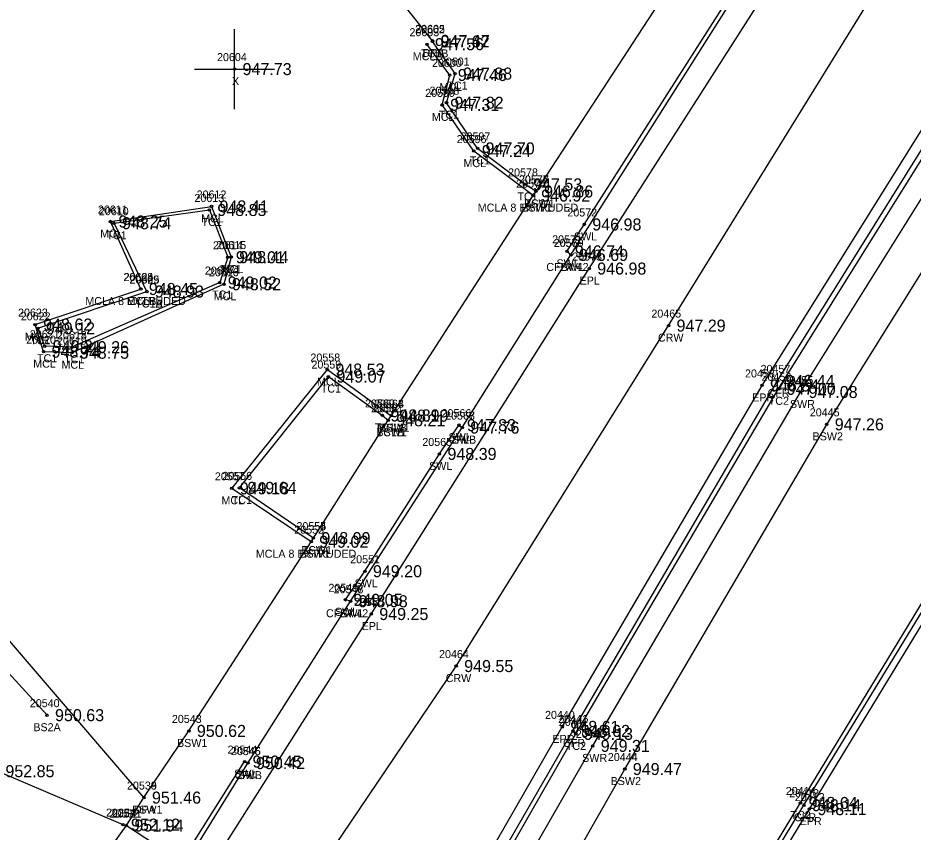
# Model space of a CAD drawing. Extents: x 1576181 to 1577685, y 1099396 to 1101490.
# Drawn here: x 1576415.2 to 1576527.1, y 1099665.2 to 1099766.9 of the extents above; entities that cross this region are included whole.
import ezdxf

# ---------------------------------------------------------------- set-up
doc = ezdxf.new("R2010")
doc.units = 0
for name, color, linetype in [('RD_DTM_BkLn1', 7, 'Continuous'), ('RD_DTM_BkLn2', 7, 'Continuous'), ('RD_DTM_BkLn_txCode', 7, 'Continuous'), ('RD_EX_Conc', 7, 'Continuous'), ('RD_EX_Conc_txCode', 7, 'Continuous'), ('RD_EX_Driveway', 7, 'Continuous'), ('RD_EX_Driveway_txCode', 7, 'Continuous'), ('RD_EX_Misc', 7, 'Continuous'), ('RD_EX_Misc_txCode', 7, 'Continuous'), ('RD_EX_Road', 7, 'Continuous'), ('RD_EX_Road_txCode', 7, 'Continuous'), ('RD_EX_TX_Conc_ELEV', 7, 'Continuous'), ('RD_EX_TX_Driveway_ELEV', 7, 'Continuous'), ('RD_EX_TX_Misc_ELEV', 7, 'Continuous'), ('RD_EX_TX_Road_ELEV', 7, 'Continuous'), ('RD_HC_Survey_ELEV', 7, 'Continuous'), ('RD_HC_Survey_txCode', 7, 'Continuous'), ('RD_SMD_Locator', 7, 'Continuous')]:
    doc.layers.add(name, color=color, linetype=linetype)

msp = doc.modelspace()

# ---------------------------------------------------------------- linework, layer by layer
at = {"layer": 'RD_DTM_BkLn1'}
msp.add_lwpolyline([(1576435.96, 1099635.47), (1576469.98, 1099685.91), (1576496.51, 1099728.46), (1576522.67, 1099770.85), (1576549.06, 1099813.4), (1576563.36, 1099837.2), (1576575.09, 1099855.95), (1576600.75, 1099898.96), (1576625.57, 1099942.14), (1576652.37, 1099988.91), (1576675.03, 1100029.12), (1576699.51, 1100072.44), (1576723.52, 1100115.7), (1576748.08, 1100158.53), (1576774.13, 1100203.85), (1576797.97, 1100246.52), (1576822.46, 1100289.82), (1576846.93, 1100333.35), (1576871.37, 1100376.46), (1576888.27, 1100406.22)], dxfattribs=at)
at = {"layer": 'RD_DTM_BkLn2'}
msp.add_line((1576418.86, 1099679.77), (1576392.78, 1099708.39), dxfattribs=at)
for points in [[(1576271.23, 1099836.06), (1576304.3, 1099797.36), (1576339.24, 1099758.21), (1576368.71, 1099722.87), (1576388.13, 1099699.72), (1576412.66, 1099672.77), (1576428.35, 1099666.09)], [(1576453.65, 1099622.74), (1576484.93, 1099677.43), (1576510.27, 1099720.56), (1576537.09, 1099763.56), (1576564.3, 1099806.82), (1576572.37, 1099816.55), (1576577.32, 1099819.84)], [(1576479.96, 1099745.23), (1576478.59, 1099746.11), (1576472.65, 1099750.61), (1576468.77, 1099756.32), (1576469.84, 1099759.96), (1576467.02, 1099763.98)], [(1576431.33, 1099732.72), (1576427.24, 1099741.26), (1576439.14, 1099742.91), (1576441.45, 1099737), (1576440.44, 1099733.84), (1576421.97, 1099725.76), (1576418.57, 1099725.88), (1576417.72, 1099728.12), (1576431.33, 1099732.72)], [(1576511.92, 1099607.05), (1576510.37, 1099614.53), (1576509.23, 1099617.04), (1576507.41, 1099618.75), (1576489.23, 1099629.49), (1576513, 1099668.8), (1576536.11, 1099706.87), (1576550.83, 1099731.33)], [(1576452.14, 1099701.9), (1576442.9, 1099708.18), (1576454.02, 1099722.09), (1576460.77, 1099717.23), (1576461.49, 1099716.63)]]:
    msp.add_lwpolyline(points, dxfattribs=at)
at = {"layer": 'RD_EX_Conc'}
for p, q in [((1576456.79, 1099694.01), (1576470.74, 1099715.71)), ((1576436.12, 1099661.14), (1576443.97, 1099673.78))]:
    msp.add_line(p, q, dxfattribs=at)
for points in [[(1576435.66, 1099661.47), (1576443.54, 1099673.97), (1576443.97, 1099673.78), (1576456.79, 1099694.01), (1576456.14, 1099694.19), (1576458.58, 1099697.76), (1576467.89, 1099712.42), (1576470.32, 1099716.02), (1576470.74, 1099715.71), (1576484.32, 1099737.29), (1576483.81, 1099737.74), (1576485.99, 1099741.1), (1576511.43, 1099781.01), (1576536.53, 1099821.05), (1576540.61, 1099827.59), (1576541.13, 1099827.37), (1576542.92, 1099831.85), (1576542.87, 1099835.12), (1576541.33, 1099839.59)], [(1576484.32, 1099737.29), (1576511.76, 1099780.7), (1576536.95, 1099820.66), (1576541.42, 1099827.15)], [(1576450.24, 1099618.33), (1576484.56, 1099677.8), (1576510.13, 1099721.55), (1576536.54, 1099763.94), (1576563.69, 1099807.11), (1576571.96, 1099817.02), (1576576.78, 1099820.05)], [(1576453.65, 1099622.74), (1576455.84, 1099621.56), (1576487.04, 1099675.93), (1576513, 1099720.16), (1576539.03, 1099761.82), (1576566.5, 1099805.38), (1576570.9, 1099812.6)], [(1576460.33, 1099619.05), (1576491.05, 1099673.04), (1576516.28, 1099716.12), (1576543.31, 1099759.42), (1576570.5, 1099802.59), (1576575.6, 1099809.12)], [(1576428.78, 1099665.98), (1576430.97, 1099669.47), (1576436.58, 1099677.8), (1576451.87, 1099701.45), (1576452.14, 1099701.9), (1576461.49, 1099716.63), (1576461.87, 1099717.2), (1576479.6, 1099744.71), (1576479.96, 1099745.23), (1576504.22, 1099782.43), (1576509.78, 1099791.57)], [(1576479.6, 1099744.71), (1576472.18, 1099750.27), (1576468.23, 1099756.05), (1576469.18, 1099759.78), (1576466.32, 1099763.63)], [(1576430.58, 1099733.03), (1576426.79, 1099741.47), (1576439.41, 1099743.35), (1576441.88, 1099737.02), (1576440.97, 1099733.63), (1576421.97, 1099725.07), (1576418.43, 1099725.2), (1576417.38, 1099728.59), (1576430.58, 1099733.03)], [(1576512.55, 1099607.18), (1576510.94, 1099614.7), (1576509.78, 1099617.42), (1576507.67, 1099619.31), (1576489.95, 1099629.7), (1576513.43, 1099668.52), (1576536.7, 1099706.66), (1576550.99, 1099730.5)], [(1576451.87, 1099701.45), (1576441.95, 1099708.12), (1576453.89, 1099722.97), (1576461.87, 1099717.2)]]:
    msp.add_lwpolyline(points, dxfattribs=at)
at = {"layer": 'RD_EX_Driveway'}
for p, q in [((1576467.04, 1099764.05), (1576453.88, 1099780.69)), ((1576430.97, 1099669.47), (1576396.23, 1099709.97))]:
    msp.add_line(p, q, dxfattribs=at)
at = {"layer": 'RD_EX_Misc'}
for p, q in [((1576442.29, 1099755.52), (1576442.29, 1099765.52)), ((1576437.29, 1099760.52), (1576447.29, 1099760.52))]:
    msp.add_line(p, q, dxfattribs=at)
at = {"layer": 'RD_EX_Road'}
for points in [[(1576217.78, 1099763.81), (1576263.48, 1099736.46), (1576283.45, 1099724.57), (1576282.38, 1099722.88), (1576302.5, 1099710.8), (1576345.46, 1099684.21), (1576368.62, 1099668.36), (1576383.76, 1099654.94), (1576386.09, 1099656.79), (1576408.06, 1099639.92), (1576408.06, 1099639.92), (1576411.91, 1099642.96), (1576420.57, 1099654.58), (1576428.78, 1099665.98), (1576435.66, 1099661.47), (1576436.12, 1099661.14), (1576438.46, 1099659.42), (1576459.37, 1099692.41), (1576486.6, 1099735.59), (1576512.85, 1099776.73), (1576539.46, 1099818.98), (1576543.78, 1099825.47), (1576541.42, 1099827.15), (1576542.92, 1099831.85)], [(1576450.24, 1099618.33), (1576449.12, 1099618.92), (1576483.24, 1099678.31), (1576508.19, 1099720.98), (1576535.39, 1099764.56), (1576562.56, 1099807.86), (1576568.65, 1099815.29), (1576571.43, 1099817.5), (1576576.56, 1099821.02), (1576582.03, 1099822.66), (1576588.16, 1099823.79), (1576596.81, 1099822.84), (1576604.56, 1099819.9), (1576624.36, 1099808.15), (1576638.14, 1099802.71)], [(1576513.37, 1099607.48), (1576511.79, 1099614.93), (1576510.39, 1099617.93), (1576508.02, 1099620.01), (1576491.05, 1099629.97), (1576514.12, 1099668.03), (1576537.42, 1099706.25), (1576551.23, 1099729.3)]]:
    msp.add_lwpolyline(points, dxfattribs=at)
at = {"layer": 'RD_SMD_Locator'}
for centre in [(1576467.02, 1099763.98), (1576467.04, 1099764.05), (1576466.32, 1099763.63), (1576442.29, 1099760.52), (1576469.18, 1099759.78), (1576469.84, 1099759.96), (1576468.23, 1099756.05), (1576468.77, 1099756.32), (1576472.65, 1099750.61), (1576472.18, 1099750.27), (1576478.59, 1099746.11), (1576479.96, 1099745.23), (1576479.96, 1099745.23), (1576479.6, 1099744.71), (1576479.6, 1099744.71), (1576439.14, 1099742.91), (1576439.41, 1099743.35), (1576426.79, 1099741.47), (1576427.24, 1099741.26), (1576485.99, 1099741.1), (1576441.45, 1099737), (1576441.88, 1099737.02), (1576483.81, 1099737.74), (1576484.32, 1099737.29), (1576484.32, 1099737.29), (1576486.6, 1099735.59), (1576440.44, 1099733.84), (1576440.97, 1099733.63), (1576430.58, 1099733.03), (1576430.58, 1099733.03), (1576431.33, 1099732.72), (1576431.33, 1099732.72), (1576417.38, 1099728.59), (1576417.72, 1099728.12), (1576496.51, 1099728.46), (1576418.57, 1099725.88), (1576418.43, 1099725.2), (1576421.97, 1099725.76), (1576421.97, 1099725.07), (1576453.89, 1099722.97), (1576454.02, 1099722.09), (1576510.13, 1099721.55), (1576508.19, 1099720.98), (1576510.27, 1099720.56), (1576513, 1099720.16), (1576460.77, 1099717.23), (1576461.87, 1099717.2), (1576461.87, 1099717.2), (1576461.49, 1099716.63), (1576461.49, 1099716.63), (1576470.32, 1099716.02), (1576516.28, 1099716.12), (1576470.74, 1099715.71), (1576470.74, 1099715.71), (1576467.89, 1099712.42), (1576441.95, 1099708.12), (1576442.9, 1099708.18), (1576451.87, 1099701.45), (1576451.87, 1099701.45), (1576452.14, 1099701.9), (1576452.14, 1099701.9), (1576458.58, 1099697.76), (1576456.14, 1099694.19), (1576456.79, 1099694.01), (1576456.79, 1099694.01), (1576459.37, 1099692.41), (1576469.98, 1099685.91), (1576418.86, 1099679.77), (1576436.58, 1099677.8), (1576483.24, 1099678.31), (1576484.56, 1099677.8), (1576484.93, 1099677.43), (1576487.04, 1099675.93), (1576443.54, 1099673.97), (1576443.97, 1099673.78), (1576443.97, 1099673.78), (1576491.05, 1099673.04), (1576430.97, 1099669.47), (1576430.97, 1099669.47), (1576513, 1099668.8), (1576513.43, 1099668.52), (1576514.12, 1099668.03), (1576428.35, 1099666.09), (1576428.78, 1099665.98), (1576428.78, 1099665.98)]:
    msp.add_circle(centre, 0.15, dxfattribs=at)

# ---------------------------------------------------------------- texts
at = {"layer": 'RD_DTM_BkLn_txCode'}
for s, p in [('20540', (1576416.71, 1099680.77)), ('BS2A', (1576417.15, 1099677.77)), ('20254', (1576426.23, 1099667.09))]:
    msp.add_text(s, height=1, dxfattribs=at).set_placement(p)
at = {"layer": 'RD_EX_Conc_txCode'}
for s, p in [('20603', (1576464.14, 1099764.63)), ('20602', (1576464.84, 1099764.98)), ('TC1B', (1576465.59, 1099761.98)), ('MCLB', (1576464.55, 1099761.63)), ('20600', (1576466.96, 1099760.78)), ('20601', (1576467.94, 1099760.96)), ('MCL', (1576467.89, 1099757.78)), ('TC1', (1576468.88, 1099757.96)), ('20599', (1576466.11, 1099757.05)), ('20598', (1576466.65, 1099757.32)), ('MCL', (1576466.94, 1099754.05)), ('TC1', (1576467.81, 1099754.32)), ('20596', (1576470.04, 1099751.27)), ('20597', (1576470.53, 1099751.61)), ('TC1', (1576471.69, 1099748.61)), ('MCL', (1576470.89, 1099748.27)), ('20578', (1576476.47, 1099747.11)), ('20576', (1576477.82, 1099746.23)), ('20577', (1576477.84, 1099746.23)), ('20574', (1576477.48, 1099745.71)), ('20575', (1576477.48, 1099745.71)), ('20612', (1576437.55, 1099744.35)), ('TC1', (1576477.63, 1099744.11)), ('20613', (1576437.28, 1099743.91)), ('TC1A', (1576478.51, 1099743.23)), ('BSW1', (1576478.48, 1099743.23)), ('20611', (1576425.22, 1099742.47)), ('20610', (1576425.34, 1099742.26)), ('MCLA 8 EXTRUDED', (1576472.67, 1099742.71)), ('BSW1', (1576478.12, 1099742.71)), ('20572', (1576483.87, 1099742.1)), ('TC1', (1576438.18, 1099740.91)), ('MCL', (1576438.12, 1099741.35)), ('MCL', (1576425.5, 1099739.47)), ('TC1', (1576426.28, 1099739.26)), ('20571', (1576481.97, 1099738.74)), ('SWL', (1576484.7, 1099739.1)), ('20614', (1576439.59, 1099738)), ('20615', (1576440.02, 1099738.02)), ('20570', (1576482.16, 1099738.29)), ('20569', (1576482.18, 1099738.29)), ('TC1', (1576440.49, 1099735)), ('MCL', (1576440.58, 1099735.02)), ('CFLA 42', (1576481.24, 1099735.29)), ('SWL', (1576482.52, 1099735.74)), ('SWL', (1576483.03, 1099735.29)), ('20608', (1576428.4, 1099734.03)), ('20624', (1576428.44, 1099734.03)), ('20617', (1576438.58, 1099734.84)), ('20616', (1576439.09, 1099734.63)), ('20609', (1576429.15, 1099733.72)), ('20625', (1576429.19, 1099733.72)), ('TC1', (1576439.48, 1099731.84)), ('MCL', (1576439.68, 1099731.63)), ('MCLA 8 EXTRUDED', (1576423.65, 1099731.03)), ('MCLB', (1576428.81, 1099731.03)), ('TC1A', (1576429.88, 1099730.72)), ('TC1B', (1576429.9, 1099730.72)), ('20623', (1576415.24, 1099729.59)), ('20622', (1576415.58, 1099729.12)), ('MCL', (1576416.09, 1099726.59)), ('20620', (1576416.25, 1099726.2)), ('20621', (1576416.71, 1099726.88)), ('TC1', (1576416.76, 1099726.12)), ('20619', (1576420.11, 1099726.07)), ('20618', (1576420.11, 1099726.76)), ('TC1', (1576417.61, 1099723.88)), ('20558', (1576451.77, 1099723.97)), ('MCL', (1576417.14, 1099723.2)), ('MCL', (1576420.67, 1099723.07)), ('TC1', (1576421.01, 1099723.76)), ('20559', (1576451.9, 1099723.09)), ('20457', (1576508.01, 1099722.55)), ('MCL', (1576452.59, 1099720.97)), ('20456', (1576508.13, 1099721.56)), ('20455', (1576510.88, 1099721.16)), ('TC1', (1576453.06, 1099720.09)), ('CFR', (1576508.9, 1099719.55)), ('20560', (1576458.59, 1099718.23)), ('TC2', (1576509.03, 1099718.56)), ('20562', (1576459.35, 1099717.63)), ('20561', (1576459.63, 1099717.63)), ('20563', (1576459.72, 1099718.2)), ('20564', (1576459.72, 1099718.2)), ('SWR', (1576511.68, 1099718.16)), ('20445', (1576514.16, 1099717.12)), ('20566', (1576468.15, 1099717.02)), ('20567', (1576468.6, 1099716.71)), ('20568', (1576468.6, 1099716.71)), ('TC1', (1576459.81, 1099715.23)), ('MCLB', (1576460.1, 1099715.2)), ('BSW1', (1576460.38, 1099715.2)), ('TC1B', (1576460.06, 1099714.63)), ('BSW1', (1576460.01, 1099714.63)), ('SWL', (1576469.03, 1099714.02)), ('BSW2', (1576514.51, 1099714.12)), ('20565', (1576465.75, 1099713.42)), ('CFLB', (1576469.06, 1099713.71)), ('SWL', (1576469.45, 1099713.71)), ('SWL', (1576466.6, 1099710.42)), ('20557', (1576439.83, 1099709.12)), ('20556', (1576440.76, 1099709.18)), ('MCL', (1576440.65, 1099706.12)), ('TC1', (1576441.94, 1099706.18)), ('20554', (1576450.02, 1099702.9)), ('20555', (1576450.02, 1099702.9)), ('20552', (1576449.75, 1099702.45)), ('20553', (1576449.75, 1099702.45)), ('MCLA 8 EXTRUDED', (1576444.94, 1099699.45)), ('BSW1', (1576450.39, 1099699.45)), ('TC1A', (1576450.69, 1099699.9)), ('BSW1', (1576450.66, 1099699.9)), ('20551', (1576456.74, 1099698.76)), ('20549', (1576454.02, 1099695.19)), ('20547', (1576454.67, 1099695.01)), ('20548', (1576454.67, 1099695.01)), ('SWL', (1576457.29, 1099695.76)), ('CFLA 42', (1576453.71, 1099692.01)), ('SWL', (1576454.84, 1099692.19)), ('SWL', (1576455.5, 1099692.01)), ('20543', (1576434.46, 1099678.8)), ('20441', (1576482.72, 1099678.8)), ('20442', (1576482.81, 1099678.43)), ('20443', (1576484.92, 1099676.93)), ('BSW1', (1576435.1, 1099675.8)), ('CFR', (1576483.33, 1099675.8)), ('20544', (1576441.42, 1099674.97)), ('20546', (1576441.83, 1099674.78)), ('20545', (1576441.85, 1099674.78)), ('TC2', (1576483.68, 1099675.43)), ('SWR', (1576485.72, 1099673.93)), ('20444', (1576488.93, 1099674.04)), ('SWL', (1576442.25, 1099671.97)), ('CFLB', (1576442.29, 1099671.78)), ('SWL', (1576442.68, 1099671.78)), ('20538', (1576428.85, 1099670.47)), ('BSW2', (1576489.28, 1099671.04)), ('20414', (1576511.16, 1099669.8)), ('20413', (1576511.59, 1099669.52)), ('20532', (1576426.66, 1099666.98)), ('BSW1', (1576429.49, 1099667.47)), ('TC2', (1576511.75, 1099666.8)), ('CFR', (1576512.2, 1099666.52))]:
    msp.add_text(s, height=1, dxfattribs=at).set_placement(p)
at = {"layer": 'RD_EX_Driveway_txCode'}
for s, p in [('20605', (1576464.86, 1099765.05)), ('DPA', (1576465.77, 1099762.05)), ('20539', (1576428.85, 1099670.47)), ('DPA', (1576429.7, 1099667.47))]:
    msp.add_text(s, height=1, dxfattribs=at).set_placement(p)
at = {"layer": 'RD_EX_Misc_txCode'}
for s, p in [('20604', (1576440.1, 1099761.52)), ('X', (1576441.97, 1099758.52))]:
    msp.add_text(s, height=1, dxfattribs=at).set_placement(p)
at = {"layer": 'RD_EX_Road_txCode'}
for s, p in [('20573', (1576484.48, 1099736.59)), ('EPL', (1576485.4, 1099733.59)), ('20458', (1576506.07, 1099721.98)), ('EPR', (1576506.96, 1099718.98)), ('20550', (1576457.21, 1099693.41)), ('EPL', (1576458.17, 1099690.41)), ('20440', (1576481.08, 1099679.31)), ('EPR', (1576482.01, 1099676.31)), ('20412', (1576512.29, 1099669.03)), ('20531', (1576426.95, 1099666.98)), ('EPR', (1576512.9, 1099666.03))]:
    msp.add_text(s, height=1, dxfattribs=at).set_placement(p)
at = {"layer": 'RD_EX_TX_Conc_ELEV'}
for s, p in [('947.56', (1576467.32, 1099762.88)), ('947.62', (1576468.02, 1099763.23)), ('947.88', (1576470.84, 1099759.21)), ('947.46', (1576470.18, 1099759.03)), ('947.31', (1576469.23, 1099755.3)), ('947.82', (1576469.77, 1099755.57)), ('947.24', (1576473.18, 1099749.52)), ('947.70', (1576473.65, 1099749.86)), ('947.53', (1576479.59, 1099745.36)), ('946.92', (1576480.6, 1099743.96)), ('946.92', (1576480.6, 1099743.96)), ('946.86', (1576480.96, 1099744.48)), ('946.86', (1576480.96, 1099744.48)), ('948.41', (1576440.41, 1099742.6)), ('948.85', (1576440.14, 1099742.16)), ('948.25', (1576427.79, 1099740.72)), ('948.74', (1576428.24, 1099740.51)), ('946.98', (1576486.99, 1099740.35)), ('946.74', (1576484.81, 1099736.99)), ('949.01', (1576442.45, 1099736.25)), ('948.44', (1576442.88, 1099736.27)), ('946.69', (1576485.32, 1099736.54)), ('946.69', (1576485.32, 1099736.54)), ('948.45', (1576431.58, 1099732.28)), ('948.45', (1576431.58, 1099732.28)), ('949.02', (1576441.44, 1099733.09)), ('948.52', (1576441.97, 1099732.88)), ('948.93', (1576432.33, 1099731.97)), ('948.93', (1576432.33, 1099731.97)), ('948.62', (1576418.38, 1099727.84)), ('949.12', (1576418.72, 1099727.37)), ('948.74', (1576419.43, 1099724.45)), ('949.21', (1576419.57, 1099725.13)), ('949.26', (1576422.97, 1099725.01)), ('948.75', (1576422.97, 1099724.32)), ('948.53', (1576454.89, 1099722.22)), ('949.07', (1576455.02, 1099721.34)), ('946.44', (1576511.13, 1099720.8)), ('947.00', (1576511.27, 1099719.81)), ('947.08', (1576514, 1099719.41)), ('948.89', (1576461.77, 1099716.48)), ('948.21', (1576462.49, 1099715.88)), ('948.21', (1576462.49, 1099715.88)), ('948.19', (1576462.87, 1099716.45)), ('948.19', (1576462.87, 1099716.45)), ('947.83', (1576471.32, 1099715.27)), ('947.76', (1576471.74, 1099714.96)), ('947.76', (1576471.74, 1099714.96)), ('947.26', (1576517.28, 1099715.37)), ('948.39', (1576468.89, 1099711.67)), ('949.18', (1576442.95, 1099707.37)), ('949.64', (1576443.9, 1099707.43)), ('948.99', (1576453.14, 1099701.15)), ('948.99', (1576453.14, 1099701.15)), ('949.02', (1576452.87, 1099700.7)), ('949.02', (1576452.87, 1099700.7)), ('949.20', (1576459.58, 1099697.01)), ('949.05', (1576457.14, 1099693.44)), ('948.98', (1576457.79, 1099693.26)), ('948.98', (1576457.79, 1099693.26)), ('950.62', (1576437.58, 1099677.05)), ('948.62', (1576485.56, 1099677.05)), ('949.13', (1576485.93, 1099676.68)), ('949.31', (1576488.04, 1099675.18)), ('950.45', (1576444.54, 1099673.22)), ('950.42', (1576444.97, 1099673.03)), ('950.42', (1576444.97, 1099673.03)), ('949.47', (1576492.05, 1099672.29)), ('951.46', (1576431.97, 1099668.72)), ('948.64', (1576514, 1099668.05)), ('948.14', (1576514.43, 1099667.77)), ('951.94', (1576429.78, 1099665.23))]:
    msp.add_text(s, height=1.5, dxfattribs=at).set_placement(p)
at = {"layer": 'RD_EX_TX_Driveway_ELEV'}
for s, p in [('947.47', (1576468.04, 1099763.3)), ('951.46', (1576431.97, 1099668.72))]:
    msp.add_text(s, height=1.5, dxfattribs=at).set_placement(p)
at = {"layer": 'RD_EX_TX_Misc_ELEV'}
for s, p in [('947.73', (1576443.29, 1099759.77)), ('950.63', (1576419.86, 1099679.02)), ('952.85', (1576413.66, 1099672.02)), ('952.12', (1576429.35, 1099665.34))]:
    msp.add_text(s, height=1.5, dxfattribs=at).set_placement(p)
at = {"layer": 'RD_EX_TX_Road_ELEV'}
for s, p in [('946.98', (1576487.6, 1099734.84)), ('946.54', (1576509.19, 1099720.23)), ('949.25', (1576460.37, 1099691.66)), ('948.61', (1576484.24, 1099677.56)), ('948.11', (1576515.12, 1099667.28)), ('951.94', (1576429.78, 1099665.23))]:
    msp.add_text(s, height=1.5, dxfattribs=at).set_placement(p)
at = {"layer": 'RD_HC_Survey_ELEV'}
for s, p in [('947.29', (1576497.51, 1099727.71)), ('949.55', (1576470.98, 1099685.16))]:
    msp.add_text(s, height=1.5, dxfattribs=at).set_placement(p)
at = {"layer": 'RD_HC_Survey_txCode'}
for s, p in [('20465', (1576494.37, 1099729.46)), ('CRW', (1576495.19, 1099726.46)), ('20464', (1576467.84, 1099686.91)), ('CRW', (1576468.67, 1099683.91))]:
    msp.add_text(s, height=1, dxfattribs=at).set_placement(p)

doc.saveas('drawing.dxf')
